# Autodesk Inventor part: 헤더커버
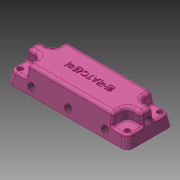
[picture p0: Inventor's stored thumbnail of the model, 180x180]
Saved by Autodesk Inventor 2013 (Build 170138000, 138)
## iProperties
Created: 2015-11
Part Number: 헤더커버
Material: 알루미늄 6061
Document SubType Name: Modeling
Designer: mduedu
Density: 2.71 g/cm^3
Mass: 159.45 g
Surface Area: 159.64 cm^2
Volume: 58.8375 cm^3
Author: mduedu
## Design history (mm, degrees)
sketch "스케치1"
  geometry: L1 (52.5, 20)-(-52.5, 20); L2 (-52.5, 20)-(-52.5, -20); L3 (-52.5, -20)-(52.5, -20); L4 (52.5, -20)-(52.5, 20); L5 (52.5, 20)-(-52.5, -20); L6 (-52.5, 20)-(52.5, -20); 1 further point
  constraints: 12 end point, 2 midpoint, 2 parallel, 1 horizontal, 1 perpendicular
  dimensions: "d0" = 105 distance of L3.end L2.end; "d1" = 40 distance of L2.end L1.end
extrude "돌출1" new body sketch "스케치1" distance "d2" = 22; taper "d3" = -10 deg
sketch "스케치2"
  geometry: L1 (-48.621, -16.121)-(-48.621, 16.121) reference; L2 (-48.621, 16.121)-(48.621, 16.121) reference; L3 (48.621, 16.121)-(48.621, -16.121) reference; L4 (48.621, -16.121)-(-48.621, -16.121) reference; L5 (-37.5, 20)-(-37.5, 5); L6 (-37.5, 5)-(-52.5, 5); L7 (37.5, 20)-(37.5, 5); L8 (37.5, 5)-(52.5, 5); L9 (37.5, -20)-(37.5, -5); L10 (37.5, -5)-(52.5, -5); L11 (-37.5, -20)-(-37.5, -5); L12 (-37.5, -5)-(-52.5, -5); L13 (52.5, 20)-(-52.5, 20) reference; L14 (-52.5, -20)-(52.5, -20) reference; L15 (-52.5, 20)-(-52.5, -20) reference; L16 (52.5, -20)-(52.5, 20) reference; 5 further points
  constraints: 16 end point, 12 point on line, 7 equal length, 4 horizontal, 3 vertical
  dimensions: "d91" = 15 distance between parallel lines of L5 L15
extrude "돌출2" cut sketch "스케치2" distance "d6" = 12; taper "d7" = 0 deg
fillet "모깎기1" dims "d8" = 5
fillet "모깎기2" dims "d9" = 1
fillet "모깎기3" dims "d10" = 5
fillet "모깎기4" dims "d11" = 2
fillet "모깎기5" dims "d12" = 3
sketch "스케치3"
  geometry: L1 (-45.5, -13)-(45.5, -13); L2 (45.5, -13)-(45.5, 13); L3 (45.5, 13)-(-45.5, 13); L4 (-45.5, 13)-(-45.5, -13); L5 (-45.5, -13)-(45.5, 13); L6 (45.5, -13)-(-45.5, 13); L7 (47.576, 20)-(-47.576, 20) reference; L8 (52.5, -15.076)-(52.5, 15.076) reference; 5 further points
  constraints: 12 end point, 4 coincident, 2 midpoint, 2 parallel, 1 horizontal, 1 perpendicular
  dimensions: "d13" = 7 distance between parallel lines of L3 L7 (= d14); "d14" = 7 distance between parallel lines of L2 L8
hole "구멍1" sketch "스케치3" at (-45.5, 13), (45.5, 13), (45.5, -13), (-45.5, -13) diameter "d15" = 4.5; stored, may be unused: countersink angle "d19" = 90 deg, drill point angle "d21" = 118 deg; dims "d16" = 6, "d17" = 4, "d18" = 2, "d20" = 8
sketch "스케치4"
  geometry: L1 (47.576, -20)-(-47.576, -20) reference; L2 (52.5, 15.076)-(52.5, -15.076) reference; L3 (-47.576, 20)-(47.576, 20) reference; L4 (-52.5, -15.076)-(-52.5, 15.076) reference; L5 (-52.5, 0)-(52.5, 0); C1 r 12.25 at (0, 0); C2 r 2.25 at (45.5, 13) reference; C3 r 2.25 at (-45.5, -13) reference; C4 r 2.25 at (45.5, -13) reference; C5 r 2.25 at (-45.5, 13) reference; C6 r 12.25 at (-32, 0); C7 r 12.25 at (32, 0); 5 further points
  constraints: 3 centre point, 2 end point, 2 midpoint, 2 point on line, 1 coincident, 4 other
  dimensions: "d22" = 24.5 diameter of C1; "d23" = 24.5 diameter of C7 (= d22); "d24" = 24.5 diameter of C6 (= d22); "d25" = 32 distance of point (0, 0) C6.centre; "d26" = 32 distance of C7.centre point (0, 0) (= d25)
extrude "돌출3" cut sketch "스케치4" distance "d27" = 9; taper "d28" = 0 deg
fillet "모깎기6" dims "d29" = 5
sketch "스케치5"
  geometry: L1 (-50.031, 14)-(-43.051, 12.769); L2 (-38.312, 10.033)-(-35.04, 6.134); L3 (-49.089, 19.347)-(-50.499, 11.347) reference; L4 (-47.576, 0)-(-52.5, 0) reference; L5 (0, 0)-(0, 22); L6 (50.031, 14)-(43.051, 12.769); L7 (38.312, 10.033)-(35.04, 6.134); A1 r 8 centre (-44.44, 4.891) between (-38.312, 10.033) and (-43.051, 12.769); A2 r 8 centre (44.44, 4.891) between (43.051, 12.769) and (38.312, 10.033); 4 further points; 1 other entity
  constraints: 10 end point, 5 symmetric about line, 4 point on circle, 3 point on line, 2 centre point, 2 tangent, 1 perpendicular, 3 other
  dimensions: "d30" = 10 distance of L1.start point (-40.183, 12.264); "d32" = 140 deg angle of L2 L1; "d35" = 8 radius of A1; "d96" = 14 vertical distance of L1.start L4.end
sketch "스케치6"
  geometry: L1 (22, -2)-(22, 2) reference; L2 (11.347, -17.999)-(19.347, -16.589) reference; L3 (10.033, -5.812)-(5.684, -2.162); L4 (0, -20)-(0, -15.076) reference; L5 (12.769, -10.551)-(14, -17.531); A1 r 8 centre (4.891, -11.94) between (12.769, -10.551) and (10.033, -5.812); 2 further points
  constraints: 4 end point, 3 point on line, 2 point on circle, 2 tangent, 1 centre point, 1 perpendicular
  dimensions: "d36" = 10 distance of L5.end point (12.264, -7.683); "d40" = 8 radius of A1; "d94" = 140 deg angle of L3 L5; "d97" = 14 horizontal distance of L5.end L4.start
node "작업점1"
node "작업점2"
node "작업점3"
hole "구멍2" diameter "d43" = 5.944; stored, may be unused: countersink angle "d49" = 90 deg, drill point angle "d51" = 0 deg; dims "d41" = 10, "d42" = 10, "d44" = 6.886, "d45" = 0.62479, "d46" = 5.959, "d47" = 4, "d48" = 2, "d50" = 6.9
hole "구멍3" diameter "d54" = 5.944; stored, may be unused: countersink angle "d60" = 90 deg, drill point angle "d62" = 0 deg; dims "d55" = 6.886, "d56" = 0.62479, "d57" = 5.959, "d58" = 4, "d59" = 2, "d61" = 6.9, "d92" = 10, "d93" = 10
hole "구멍4" diameter "d65" = 5.944; stored, may be unused: countersink angle "d71" = 90 deg, drill point angle "d73" = 0 deg; dims "d63" = 10, "d64" = 10, "d66" = 6.886, "d67" = 0.62479, "d68" = 5.959, "d69" = 4, "d70" = 2, "d72" = 6.9
sketch "스케치7"
  geometry: C1 r 2.972 at (15.076, 14.216) reference; 1 further point
sketch "스케치8"
  geometry: C1 r 2.972 at (15.076, 14.216) reference; 1 further point
sketch "스케치9"
  geometry: C1 r 2.972 at (47.576, 14.216) reference; 1 further point
feature "스윕1" dims "d74" = 0
feature "스윕2" dims "d75" = 0
feature "스윕3" dims "d76" = 0
sketch "스케치10"
  geometry: L1 (15.576, 9)-(15.576, 0); L2 (47.576, 9)-(47.576, 3.473); L3 (79.576, 9)-(79.576, 0); 8 further points; 3 other entities
  constraints: 6 end point, 3 point on line, 2 horizontal alignment, 2 vertical, 2 vertical alignment, 1 parallel, 6 other
  dimensions: "d77" = 6 dimension on point (15.576, 6)
hole "구멍5" sketch "스케치10" diameter "d78" = 5.944; stored, may be unused: countersink angle "d84" = 90 deg, drill point angle "d86" = 0 deg; dims "d79" = 6.886, "d80" = 0.62479, "d81" = 5.959, "d82" = 4, "d83" = 2, "d85" = 6.9
sketch "스케치11"
  geometry: C1 r 2.972 at (0, 0) reference; C2 r 2.972 at (32, 0) reference; C3 r 2.972 at (64, 0) reference; 1 further point
extrude "돌출4" cut sketch "스케치11" distance "d87" = 8; taper "d88" = 0 deg
sketch "스케치12"
  geometry: 2 further points
  constraints: 1 coincident, 1 other
feature "엠보싱1" sketch "스케치12" dims "d0" = 105, "d1" = 40, "d9" = 1, "d89" = 0.5, "d90" = 0
node "솔리드1"
node "투영된 루프1"
node "절단 모서리 투영1"
